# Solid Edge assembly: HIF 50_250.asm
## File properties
Title: Zylinder
Author: ahadarics
Template: iso assembly.asm
Last saved by: ahadarics
Revision: 38
Application: Solid Edge
Username: ahadarics
Dokumentum tartalom típus: 1
Document Number: HIF 50/250
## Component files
Kit_2.par
Kit_1.par
Profilrohr 50_250.par
Kolbenstange 50_250.par
Mutter.par
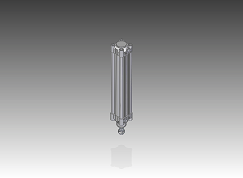
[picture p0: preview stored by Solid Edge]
